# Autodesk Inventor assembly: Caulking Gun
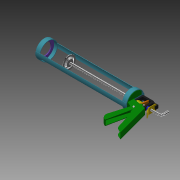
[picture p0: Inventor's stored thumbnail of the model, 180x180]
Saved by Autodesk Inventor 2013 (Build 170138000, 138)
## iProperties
Created: 2009-03
Part Number: Caulking Gun
Document SubType Name: Assembly
Designer: tangg
Mass: 1178.56 g
Surface Area: 1624.46 cm^2
Volume: 273.486 cm^3
Density: 4.30939 g/cm^3
Author: tangg
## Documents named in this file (13)
- C:\Users\boganb\Documents\B2 Design\Goodyear\2013 Tutorial Files\Stress Analysis Contacts\Caulk Gun.iam
- C:\Users\boganb\Documents\B2 Design\Goodyear\2013 Tutorial Files\Stress Analysis Contacts\Plunger.ipt
- C:\Users\boganb\Documents\B2 Design\Goodyear\2013 Tutorial Files\Stress Analysis Contacts\Main Frame.ipt
- C:\Users\boganb\Documents\B2 Design\Goodyear\2013 Tutorial Files\Stress Analysis Contacts\Handle.ipt
- C:\Users\boganb\Documents\B2 Design\Goodyear\2013 Tutorial Files\Stress Analysis Contacts\Trigger.ipt
- C:\Users\boganb\Documents\B2 Design\Goodyear\2013 Tutorial Files\Stress Analysis Contacts\Actuator.ipt
- C:\Users\boganb\Documents\B2 Design\Goodyear\2013 Tutorial Files\Stress Analysis Contacts\Caulk Tube.ipt
- C:\Users\boganb\Documents\B2 Design\Goodyear\2013 Tutorial Files\Stress Analysis Contacts\Pin.ipt
- C:\Users\boganb\Documents\B2 Design\Goodyear\2013 Tutorial Files\Stress Analysis Contacts\Actuator Spring.ipt
- C:\Users\boganb\Documents\B2 Design\Goodyear\2013 Tutorial Files\Stress Analysis Contacts\Front Frame.ipt
- C:\Users\boganb\Documents\B2 Design\Goodyear\2013 Tutorial Files\Stress Analysis Contacts\Ring.ipt
- C:\Users\boganb\Documents\B2 Design\Goodyear\2013 Tutorial Files\Stress Analysis Contacts\Lock.ipt
- C:\Users\boganb\Documents\B2 Design\Goodyear\2013 Tutorial Files\Stress Analysis Contacts\Lock Spring.ipt
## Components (12 placed, 12 different names)
1. Main Frame:1 — Flush:1, Flush:2, Flush:3, Mate:30, Flush:5, Mate:44, Flush:11, Mate:54, Mate:57, Flush:15
2. Front Frame:1 — Mate:39, Flush:11, Mate:51, Mate:58
3. Caulk Tube:1 — Mate:31
4. Handle:1 — Flush:2, Mate:27, Mate:33, Flush:5, Mate:39
5. Plunger:1 — Flush:1, Mate:27, Mate:30, Mate:31, Flush:8, Mate:43, Flush:14, Mate:49, Mate:50, Mate:53, Mate:56
6. Trigger:1 — Flush:3, Mate:34, Tangent:1, Mate:59
7. Pin:1 — Mate:33, Mate:34, Mate:59
8. Actuator:1 — Tangent:1, Flush:14, Mate:49, Mate:50
9. Actuator Spring:1 — Mate:43, Mate:44
10. Ring:1 — Mate:51, Mate:58
11. Lock:1 — Mate:56, Mate:57, Flush:15
12. Lock Spring:2 — Mate:53, Mate:54
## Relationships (26: Mate 17, Flush 8, Tangent 1)
- Flush:1: Main Frame:1 ↔ Plunger:1
- Flush:2: Main Frame:1 ↔ Handle:1
- Flush:3: Main Frame:1 ↔ Trigger:1
- Mate:27: Handle:1 ↔ Plunger:1
- Mate:30: Main Frame:1 ↔ Plunger:1
- Mate:31: Caulk Tube:1 ↔ Plunger:1
- Mate:33: Handle:1 ↔ Pin:1
- Mate:34: Trigger:1 ↔ Pin:1
- Flush:5: Main Frame:1 ↔ Handle:1
- Flush:8: Plunger:1
- Mate:39: Front Frame:1 ↔ Handle:1
- Mate:43: Plunger:1 ↔ Actuator Spring:1
- Mate:44: Main Frame:1 ↔ Actuator Spring:1
- Flush:11: Main Frame:1 ↔ Front Frame:1
- Tangent:1: Trigger:1 ↔ Actuator:1
- Flush:14: Plunger:1 ↔ Actuator:1
- Mate:49: Plunger:1 ↔ Actuator:1
- Mate:50: Plunger:1 ↔ Actuator:1
- Mate:51: Front Frame:1 ↔ Ring:1
- Mate:53: Plunger:1 ↔ Lock Spring:2
- Mate:54: Main Frame:1 ↔ Lock Spring:2
- Mate:56: Plunger:1 ↔ Lock:1
- Mate:57: Main Frame:1 ↔ Lock:1
- Flush:15: Main Frame:1 ↔ Lock:1
- Mate:58: Front Frame:1 ↔ Ring:1
- Mate:59: Trigger:1 ↔ Pin:1
## Named parameters: sa_14 = 14496.5324 mm, sa_15 = -3853.64091 mm, sa_16 = 0 mm, sa_17 = -14488.88739 mm, sa_18 = -3882.28568 mm, sa_19 = 0 mm, sa_20 = 20000 mm, sa_21 = 0, sa_22 = 0, sa_23 = -20000 mm, sa_24 = 0 mm, sa_25 = 0 mm, sa_27 = 0
